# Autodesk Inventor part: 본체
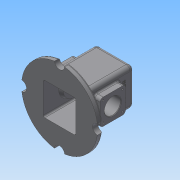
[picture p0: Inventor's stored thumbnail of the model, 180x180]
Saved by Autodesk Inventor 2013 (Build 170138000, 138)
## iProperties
Created: 2018-07
Part Number: 본체
Material: 일반
Document SubType Name: Modeling
Designer: Administrator
Density: 1 g/cm^3
Author: Administrator
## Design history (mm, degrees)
sketch "스케치1"
  geometry: L1 (-37, -37)-(37, -37); L2 (37, -37)-(37, 37); L3 (37, 37)-(-37, 37); L4 (-37, 37)-(-37, -37); L5 (-37, -37)-(37, 37); L6 (37, -37)-(-37, 37); 1 further point
  constraints: 12 end point, 2 midpoint, 2 parallel, 1 horizontal, 1 perpendicular
  dimensions: "d0" = 74 distance of L2.end L3.end; "d2" = 74 distance of L1.end L2.end
extrude "돌출1" new body sketch "스케치1" distance "d3" = 110; taper "d4" = 0 deg
feature "쉘1" dims "d5" = 5
sketch "스케치2"
  geometry: L1 (0, 0)-(74, 0) reference; L2 (12, 30)-(62, 30); L3 (62, 30)-(62, 80); L4 (62, 80)-(12, 80); L5 (12, 80)-(12, 30); L6 (12, 30)-(62, 80); L7 (62, 30)-(12, 80); 4 further points
  constraints: 12 end point, 4 midpoint, 2 parallel, 1 horizontal, 1 perpendicular, 1 vertical alignment
  dimensions: "d6" = 50 distance of L2.end L3.end; "d8" = 50 distance of L3.end L4.end; "d9" = 55 distance from line of L1 point (37, 55)
extrude "돌출2" join sketch "스케치2" distance "d10" = 13; taper "d11" = 0 deg
sketch "스케치3"
  geometry: L1 (0, 0)-(-64, 0) reference; C1 r 25 at (-32, 55); 2 further points
  constraints: 1 centre point, 1 midpoint, 1 vertical alignment
  dimensions: "d12" = 50 diameter of C1; "d13" = 55 distance from line of C1.centre L1
extrude "돌출3" join sketch "스케치3" distance "d14" = 7; taper "d15" = -20 deg
hole "구멍1" diameter "d18" = 32; stored, may be unused: countersink angle "d22" = 90 deg, drill point angle "d24" = 118 deg; dims "d16" = 10, "d17" = 10, "d19" = 6, "d20" = 4, "d21" = 2, "d23" = 8
sketch "스케치4"
  geometry: L1 (37, -37)-(-37, -37) reference; L2 (37, 37)-(37, -37) reference; L3 (-37, 37)-(37, 37) reference; L4 (-37, -37)-(-37, 37) reference; C1 r 75 at (0, 0); 1 further point
  constraints: 1 centre point, 1 coincident
  dimensions: "d25" = 150 diameter of C1
extrude "돌출4" join sketch "스케치4" distance "d26" = 10; taper "d27" = 0 deg
sketch "스케치5"
  geometry: L1 (-20, -20)-(20, -20); L2 (20, -20)-(20, 20); L3 (20, 20)-(-20, 20); L4 (-20, 20)-(-20, -20); L5 (-20, -20)-(20, 20); L6 (20, -20)-(-20, 20); 3 further points
  constraints: 12 end point, 3 midpoint, 2 parallel, 1 coincident, 1 horizontal, 1 perpendicular
  dimensions: "d28" = 40 distance of L1.end L2.end; "d30" = 40 distance of L2.end L3.end
extrude "돌출5" join sketch "스케치5" distance "d31" = 7; taper "d32" = 0 deg
sketch "스케치6"
  geometry: C1 r 17.5 at (0, 0); 1 further point
  constraints: 1 centre point, 1 coincident
  dimensions: "d33" = 35 diameter of C1
extrude "돌출6" join sketch "스케치6" distance "d34" = 3; taper "d35" = 0 deg
hole "구멍2" diameter "d38" = 21; stored, may be unused: countersink angle "d42" = 90 deg, drill point angle "d44" = 118 deg; dims "d36" = 10, "d37" = 10, "d39" = 6, "d40" = 28, "d41" = 4, "d43" = 8
sketch "스케치7"
  geometry: C1 r 10 at (-75, 0); C2 r 10 at (75, 0); C3 r 10 at (0, -75); C4 r 10 at (0, 75); A1 r 75 centre (0, 0) between (-75, 0) and (75, 0) reference
  constraints: 4 centre point, 4 point on circle, 2 horizontal alignment, 2 vertical alignment
  dimensions: "d46" = 20 diameter of C1; "d47" = 20 diameter of C2; "d48" = 20 diameter of C3; "d49" = 20 diameter of C4
extrude "돌출7" cut sketch "스케치7" stored distance "d50" = 3; taper "d51" = 0 deg
fillet "모깎기1" dims "d52" = 6
sketch "스케치8"
  geometry: A1 r 6 centre (56, 74) between (62, 74) and (56, 80) reference; A2 r 6 centre (18, 74) between (18, 80) and (12, 74) reference; A3 r 6 centre (18, 36) between (12, 36) and (18, 30) reference; A4 r 6 centre (56, 36) between (56, 30) and (62, 36) reference; 5 further points
  constraints: 4 coincident
hole "구멍3" sketch "스케치8" at (18, 74), (18, 36), (56, 36), (56, 74) diameter "d53" = 3.242; stored, may be unused: countersink angle "d57" = 82 deg, drill point angle "d59" = 118 deg; dims "d54" = 8, "d55" = 3.023, "d56" = 4, "d58" = 10
fillet "모깎기2" dims "d60" = 8
fillet "모깎기3" dims "d61" = 3
chamfer "모따기1" distance "d62" = 1; stored, may be unused: second distance "d63" = 2, angle "d64" = 45 deg
sketch "스케치9"
  geometry: L1 (46.5, 18)-(11.5, 18) reference; L2 (66, -89)-(66, 0) reference; 2 further points
  constraints: 1 other
  dimensions: "d65" = 30 distance from line of point (29, -12) L1; "d66" = 37 distance from line of L2 point (29, -12)
feature "엠보싱1" sketch "스케치9" dims "d0" = 74, "d2" = 74, "d67" = 0.5, "d68" = 0
node "솔리드1"
mirror "대칭1"
mirror "대칭2"
